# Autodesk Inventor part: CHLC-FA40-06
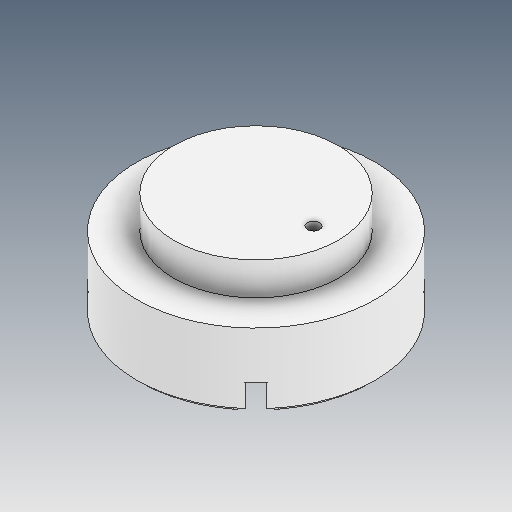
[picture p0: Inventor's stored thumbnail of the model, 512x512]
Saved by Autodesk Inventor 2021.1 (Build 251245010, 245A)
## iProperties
Created: 2021-05
Part Number: CHLC-FA40-06
Material: Ogólny
Document SubType Name: Modeling
Designer: user
Density: 1 g/cm^3
Appearance: Domyślna
Author: user
Revision Number: ÈÎºÎ
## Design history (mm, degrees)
feature "ÇÐ³ý-À­Éì4"
node "Bryła1"
